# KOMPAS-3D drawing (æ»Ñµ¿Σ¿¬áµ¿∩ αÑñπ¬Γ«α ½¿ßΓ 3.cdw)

Referenced files: 2.cdw
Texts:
  ПЛК.303120.01 СП
  Назаров
  Шайба 6 Л ГОСТ 6402-70
  Шайба пружинная
  Шайба
  ГОСТ
  Сборочный чертеж
  Кольцо 75 ГОСТ13941-86
  ПШП. РЧО.140.00.00 СБ-
  Шпонки ГОСТ 23360-78
  Штифт 8х7 ГОСТ 3912-78
Dimensions and other numbers on the sheet: 65Г; 029; 70; 1:1; 1; 3; 20х12х80; 10х8х50; 46; 47; 20х12х90; 2; 43; 44; 45; 48; 0; 4; 5; 6; 7; 8; 9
